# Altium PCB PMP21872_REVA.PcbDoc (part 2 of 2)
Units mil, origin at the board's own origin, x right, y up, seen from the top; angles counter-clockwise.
Board outline 2225 x 1350 mil, 4 copper layers (Top Layer, Signal Layer 1, Signal Layer 2, Bottom Layer), stack 61.6 mil thick; 75 components, 39 nets, 233 pads, 165 vias.
Unrouted connection lines stored in the file: 51.
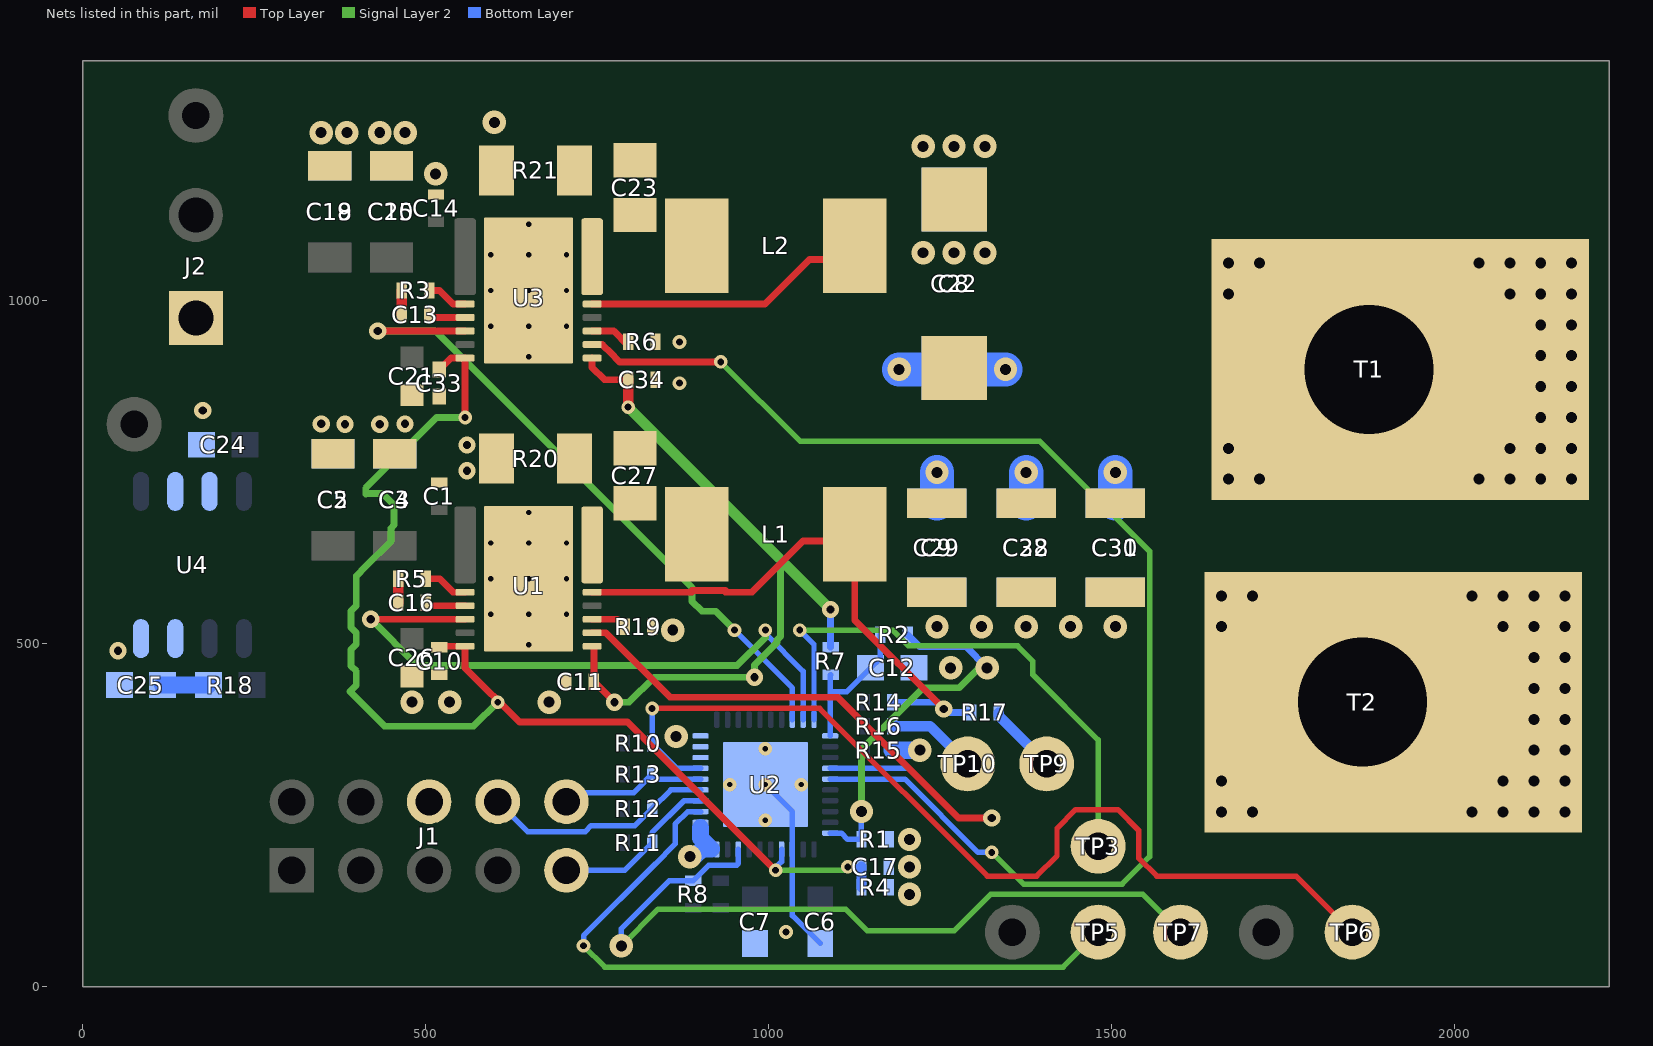
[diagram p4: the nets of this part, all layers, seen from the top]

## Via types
v1: diameter 32, hole 16, Top Layer to Bottom Layer, 56 vias
v2: diameter 34, hole 16, Top Layer to Bottom Layer, tented both sides, 45 vias
v3: diameter 19.68, hole 7.87, Top Layer to Bottom Layer, 27 vias
v4: diameter 20, hole 10, Top Layer to Bottom Layer, tented both sides, 19 vias
v5: diameter 25, hole 12, Top Layer to Bottom Layer, tented both sides, 18 vias

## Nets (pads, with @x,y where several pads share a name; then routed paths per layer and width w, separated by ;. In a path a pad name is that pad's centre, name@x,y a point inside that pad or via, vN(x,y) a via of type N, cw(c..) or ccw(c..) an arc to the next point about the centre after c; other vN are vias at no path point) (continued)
GND: C1.2 C2.2 C3.2 C4.2 C5.2 C6.2 C7.2 C8.2 C9.2 C10.2 C11.2 C12.2 C14.2 C15.2 C17.2 C18.2 C19.2 C20.2 C21.2 C22.2 C24.2 C25.2 C26.2 C28.2 C29.2 C30.2 C31.2 C32.2 C33.2 C34.2 J1.6 J2.1 R1.1 R4.1 R6.1 R15.1 R19.1 R20.2 R21.2 T2.1 U1.13@650,595 U2.13 U2.20 U2.21 U2.22 U2.28 U2.29 U2.30 U2.41@995,295 U3.13@650,1015 U4.3 U4.4 | length 378.2
  Bottom Layer w8: v3(995,295) 1034.37,255.63 U2.13@1034.37,200.51 1034.37,104.13 C6.2@1075,63.5
  Bottom Layer w25: v2(885,190) 891.77,190 902.97,201.2 916.44,201.2 900.51,217.13 U2.21@900.51,224.13 900.51,232.13 ; R15.1@1180,345 v2(1220,345)
  other v1: 1660,255 1705,255 2025,255 2070,255 2115,255 2160,255 1660,300 2070,300 2115,300 2160,300 2115,345 2160,345 2115,390 2160,390 2115,435 2160,435 2115,480 2160,480 1660,525 2070,525 2115,525 2160,525 1660,570 1705,570 2025,570 2070,570 2115,570 2160,570
  other v2: 1205,135 1205,175 1205,215 865,365 480,415 535,415 680,415 1265,465 860,520 1245,525 1310,525 1375,525 1440,525 1505,525 1225,1070 1270,1070 1315,1070 514.5,1185 1225,1225 1270,1225 1315,1225 347.7,1245 385.09,1245 433,1245 470,1245 600,1260
  other v3: 995,242.83 942.83,295 1047.17,295 995,347.17 650,498.54 594.88,543.03 650,543.03 705.12,543.03 594.88,595 650,595 705.12,595 594.88,646.97 650,646.97 705.12,646.97 650,691.46 650,918.54 594.88,963.03 650,963.03 705.12,963.03 594.88,1015 650,1015 705.12,1015 594.88,1066.97 650,1066.97 705.12,1066.97 650,1111.46
  other v4: 1025,80 870,880 870,940
  other v5: 51.73,490 560,752.27 560,790 382.26,820 433,820 347.7,820.66 470,820.66 175,840
Gnd_remote: R16.2 TP10.1 | length 132.8
  Bottom Layer w15: R16.2@1180,380 1235,380 TP10.1@1290,325
NetC13_1: C13.1 U3.9 | length 54.3
  Top Layer w10: C13.1@505,980 509.38,975.62 U3.9@557.48,975.62
NetC13_2: C13.2 R3.1 | length 35
  Top Layer w15: C13.2@465,980 R3.1@465,1015
NetC16_1: C16.1 U1.9 | length 59.3
  Top Layer w10: C16.1@500,560 504.38,555.62 U1.9@557.48,555.62
NetC16_2: C16.2 R5.1 | length 35
  Top Layer w15: C16.2@460,560 R5.1@460,595
NetC23_1: C23.1 L2.1 U3.6
NetC23_2: C23.2 R21.1
NetC25_1: C25.1 R18.1 | length 67
  Bottom Layer w25: C25.1@116.5,440 R18.1@183.5,440
NetC27_1: C27.1 L1.1 U1.6
NetC27_2: C27.2 R20.1
NetR1_2: R1.2 R2.2 U2.10 | length 548.5
  Signal Layer 2 w10: v2(1135,255.63) 1135,346 1225,436 1277.01,436 1306.01,465 v2(1318.3,465)
  Bottom Layer w8: U2.10@1089.49,224.13 1105.87,224.13 1115,215 R1.2@1135,215 v2(1135,255.63)
  Bottom Layer w10: R2.2@1202.56,513.06 1219.62,496 1287.3,496 v2(1318.3,465)
NetR3_2: R3.2 U3.8 | length 60.6
  Top Layer w10: R3.2@505,1015 520.18,1015 539.87,995.31 U3.8@557.48,995.31
NetR5_2: R5.2 U1.8 | length 65.6
  Top Layer w10: R5.2@500,595 520.18,595 539.87,575.31 U1.8@557.48,575.31
NetR6_2: R6.2 U3.3 | length 61.1
  Top Layer w10: U3.3@742.52,955.93 774.07,955.93 R6.2@795,935
NetR19_2: R19.2 U1.3 | length 52
  Top Layer w10: U1.3@742.52,535.93 779.07,535.93 R19.2@790,525
NetU4_6: U4.6 U4.7
PMB_ALERT#: J1.8 R12.1 U2.25 | length 338.6
  Bottom Layer w8: J1.8@605,270 648.48,226.52 732.74,226.52 741.22,235 805,235 R12.1@830,260 857.13,287.13 U2.25@900.51,287.13
PMB_CLK: J1.9 R11.1 U2.24 | length 246.3
  Bottom Layer w8: J1.9@705,170 790,170 R11.1@830,210 830,224.94 876.43,271.38 U2.24@900.51,271.38
PMB_DIO: J1.10 R13.1 U2.26 | length 215
  Bottom Layer w8: J1.10@705,270 718,283 803,283 R13.1@830,310 837.13,302.87 U2.26@900.51,302.87
PWM1: U1.10 U2.39 | length 921.5
  Top Layer w10: v5(420,535.93) U1.10@557.48,535.93
  Signal Layer 2 w10: v5(420,535.93) 487.63,468.3 953.93,468.3 995,509.37 v4(995,520)
  Bottom Layer w8: v4(995,520) 995,515 1050.12,459.88 U2.39@1050.12,389.49
PWM2: U2.38 U3.10 | length 1005.2
  Top Layer w10: v5(430,955.93) U3.10@557.48,955.93
  Signal Layer 2 w10: v5(430,955.93) 514.07,955.93 888.1,581.9 888.1,562 902.45,547.65 922.35,547.65 v4(950,520)
  Bottom Layer w8: v4(950,520) 1034.37,435.63 U2.38@1034.37,389.49
TSEN: C10.1 C17.1 C33.1 R4.2 U1.12 U2.14 U3.12 | length 1773.1
  Top Layer w10: C10.1@520,495 521.55,496.55 U1.12@557.48,496.55 557.48,465.02 636.5,386 794,386 v4(1010,170) ; C33.1@520,899.68 536.87,916.55 U3.12@557.48,916.55 v4(557.48,830.02)
  Signal Layer 2 w8: v4(1010,170) 1110,170 v4(1115,175)
  Signal Layer 2 w10: v4(557.48,830.02) 515.77,830.02 412.6,726.85 412.6,718.61 412.99,719 437.01,719 452.5,703.51 454,702.01 454,677.99 454,672.99 449.5,668.49 449.5,649.5 412.6,612.6 398.86,598.86 398.86,555.81 391,547.94 391,523.92 398.86,516.05 398.86,499.87 391,492.01 391,467.98 398.86,460.12 398.86,439.81 389.56,430.5 440.06,380 570,380 v4(605,415)
  Bottom Layer w8: v4(1010,170) 1010,174.06 1018.62,182.68 U2.14@1018.62,200.51 ; v4(1115,175) C17.1@1135,175
  Bottom Layer w15: R4.2@1135,145 C17.1@1135,175
VCCIO_EN: TP5.1 U2.23 | length 1071.8
  Signal Layer 2 w8: v4(730,60) 761,29 1429,29 TP5.1@1480,80 ; TP5.1@1472.5,87.5 TP5.1@1480,95
  Bottom Layer w8: v4(730,60) 730,75 833.79,178.79 833.84,178.79 863.5,208.44 863.5,237.23 881.9,255.63 U2.23@900.51,255.63
VOUT: C8.1 C9.1 C22.1 C28.1 C29.1 C30.1 C31.1 C32.1 L1.2 L2.2 R14.1 R17.1 T1.1 U1.5 U3.5 | length 1550.7
  Top Layer w10: U1.5@742.52,575.31 888.1,575.31 888.1,578 937.1,578 937.1,575.31 975.31,575.31 1050,650 L1.2@1125.16,650 ; U3.5@742.52,995.31 994.68,995.31 1059.37,1060 L2.2@1125.16,1060 ; L1.2@1125.16,660 L1.2@1125.16,650 ; v5(1255,405) 1125.16,534.84 L1.2@1125.16,650
  Bottom Layer w10: R14.1@1180,415 1245,415 v5(1255,405) 1260,400 R17.1@1295,400
  Bottom Layer w50: v2(1190,900) C22.1@1270,900 ; C29.1@1245,704.96 v2(1245,750) ; C22.1@1270,902.17 C22.1@1270,900 ; v2(1345,900) C22.1@1270,900 ; C32.1@1375,704.96 v2(1375,750) ; C31.1@1505,704.96 v2(1505,750)
  other v1: 1670,740 1715,740 2035,740 2080,740 2125,740 2170,740 1670,785 2080,785 2125,785 2170,785 2125,830 2170,830 2125,875 2170,875 2125,920 2170,920 2125,965 2170,965 1670,1010 2080,1010 2125,1010 2170,1010 1670,1055 1715,1055 2035,1055 2080,1055 2125,1055 2170,1055
Vout_CSP1: U1.2 U2.4 | length 960.1
  Top Layer w10: U1.2@742.52,516.24 762.29,516.24 856.23,422.3 1100.12,422.3 1276.21,246.22 v5(1325,246.22)
  Bottom Layer w8: U2.4@1089.49,318.62 1203.8,318.62 1276.59,245.84 v5@1324.62,245.84
  Bottom Layer w10: v5@1324.62,245.84 v5(1325,246.22)
Vout_CSP2: U2.5 U3.2 | length 1927.7
  Top Layer w10: U3.2@742.52,936.24 757.29,936.24 760.06,933.47 760.12,933.47 768.3,925.29 768.3,925.23 782.53,911 v4(929.91,911)
  Signal Layer 2 w8: v4(929.91,911) 1045.91,795 1395,795 1555,635 1555,190 1515,150 1371.22,150 v4(1325,196.22)
  Bottom Layer w8: U2.5@1089.49,302.87 1198.34,302.87 1304.99,196.22 v4(1325,196.22)
Vout_SKIP: TP3.1 U2.40 | length 811.9
  Signal Layer 2 w8: v4@1040,520 v4(1045,520) 1180.44,520 1203.44,497 1362.6,497 1385,474.6 1385,455 1480,360 TP3.1@1480,205
  Bottom Layer w8: v4(1045,520) 1065.87,499.13 U2.40@1065.87,389.49
VR_FAULT#: R10.1 TP6.1 U2.27 | length 1419.3
  Top Layer w8: v4(830,405.98) 1074.02,405.98 1318.62,161.38 1390.36,161.38 1420,191.01 1420,231.22 1447.24,258.46 1508.85,258.46 1538.93,228.38 1538.93,187.93 1565.48,161.38 1768.62,161.38 TP6.1@1850,80
  Bottom Layer w8: v4(830,405.98) R10.1@830,355 866.38,318.62 U2.27@900.51,318.62
VR_HOT: R8.1 TP7.1 U2.18 | length 1150.3
  Signal Layer 2 w8: v2(785,60) 838.52,113.52 1111.88,113.52 1143.4,82 1270.39,82 1323.39,135 1545,135 TP7.1@1600,80
  Bottom Layer w8: v2(785,60) 785,85 855,155 R8.1@890,155 912.7,177.7 953.07,177.7 955.63,180.26 U2.18@955.63,200.51
VREF: C12.1 R2.1 R7.1 U2.1 | length 216.7
  Bottom Layer w8: U2.1@1089.49,365.87 1089.49,429.76 1089.72,430 ; R7.1@1090,455 1089.49,454.49 1089.49,430.24 1089.72,430 ; R2.1@1162.56,513.06 1162.56,479.06 C12.1@1148.5,465 1113.5,430 1089.72,430
VREF_P: C11.1 C34.1 R7.2 U1.1 U3.1 | length 1083.2
  Top Layer w10: U1.1@742.52,496.55 745,494.07 C11.1@745,445 v5(775,415) ; U3.1@742.52,916.55 742.52,902.8 760.32,885 C34.1@795,885
  Top Layer w15: v4(795,845) C34.1@795,885
  Signal Layer 2 w10: v5(775,415) 796.17,415 832.47,451.3 v5(979.1,451.3) 979.1,469.43 1012,502.33 1012,505.89 1017,510.89 1017,609.05 1023.98,616.02
  Signal Layer 2 w15: v4(795,845) 1023.98,616.02 v5(1090,550)
  Bottom Layer w10: R7.2@1090,495 v5(1090,550)
Vremote+: R17.2 TP9.1 | length 104
  Bottom Layer w15: R17.2@1335,400 1335,395 TP9.1@1405,325
pads on no net: J1.1 J1.2 J1.3 J1.4 J1.5 J1.7 U1.13@618.31,517.05 U1.13@618.31,569.02 U1.13@618.31,620.98 U1.13@618.31,672.95 U1.13@681.69,517.05 U1.13@681.69,569.02 U1.13@681.69,620.98 U1.13@681.69,672.95 U2.7 U2.8 U2.9 U2.15 U2.19 U2.31 U2.32 U2.33 U2.34 U2.35 U2.36 U2.37 U2.41@964.09,264.09 U2.41@964.09,325.91 U2.41@1025.91,264.09 U2.41@1025.91,325.91 U3.13@618.31,937.05 U3.13@618.31,989.02 U3.13@618.31,1040.98 U3.13@618.31,1092.95 U3.13@681.69,937.05 U3.13@681.69,989.02 U3.13@681.69,1040.98 U3.13@681.69,1092.95 U4.5

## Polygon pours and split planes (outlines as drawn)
12Vin on Top Layer "TOP_LAYER_12VIN_P030" (solid, remove dead copper, pour order 30): 113.41,1325 113.9,1324.51 215,1324.51 215,1263.15 210.97,1259.12 327.96,1142.14 578.4,1142.14 577.18,1140.92 577.18,1004.16 540.48,1004.16 520,1024.64 520,1040 332.95,1040 327.96,1035 327.96,722.04 335,715 335.08,715.08 580,715.08 580,577.13 577.13,580 545,580 505,620 295,620 210,705 210,1075 112.86,1075 113.41,1075.54
GND on Top Layer "TOP_LAYER_GND_P040" (solid, remove dead copper, pour order 40): 0,0 0,1330 2225,1330 2225,0
GND on Signal Layer 1 "SIGNAL_LAYER_1_GND_P042" (solid, remove dead copper, pour order 42): 0,0 0,1330 2225,1330 2225,0
GND on Signal Layer 2 "SIGNAL_LAYER_2_GND_P044" (solid, remove dead copper, pour order 44): 0,0 0,1330 2225,1330 2225,0
12Vin on Bottom Layer "BOTTOM_LAYER_12VIN_P038" (solid, remove dead copper, pour order 38): 113.41,1325 113.9,1324.51 215,1324.51 215,1263.15 210.97,1259.12 327.96,1142.14 578.4,1142.14 577.18,1140.92 577.18,1004.16 540.48,1004.16 520,1024.64 520,1040 332.95,1040 327.96,1035 327.96,722.04 335,715 335.08,715.08 580,715.08 580,577.13 577.13,580 545,580 505,620 295,620 210,705 210,1075 112.86,1075 113.41,1075.54
GND on Bottom Layer "BOTTOM_LAYER_GND_P046" (solid, remove dead copper, pour order 46): 0,0 0,1330 2225,1330 2225,0

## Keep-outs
Keep-Out Layer:
  text ".Layer_Name" at 577,-858.49 h60

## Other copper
Top Layer:
  region net VOUT: 1075,1155 1075,590 1170,590 1230,650 2195,650 2195,1100 1640,1100 1575,1035 1210,1035 1180,1065 1180,1155
  region net NetC23_2: 690,1230 690,1155 755,1155 775,1175 840,1175 840,1230
  region net NetC23_1: 730,1010 730,1110 775,1155 945,1155 945,1010
  region net NetC27_2: 690,810 690,735 755,735 775,755 840,755 840,810
  region net NetC27_1: 730,590 730,690 775,735 945,735 945,590
  text ".Layer_Name" at 577,-858.49 h60
Bottom Layer:
  region net VOUT: 1165,980 1165,650 2195,650 2195,1100 1640,1100 1520,980
  region net 5V: 175,535 175,480 195,480 220,455 220,420 270,420 270,535
  region net NetU4_6: 125,750 125,695 195,695 195,750
  region net 12Vin: 1050,215 1050,105 1095,105 1095,185 1065,215
  text ".Layer_Name" at 577,-858.49 h60

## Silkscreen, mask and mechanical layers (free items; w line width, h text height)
Top Overlay:
  text ".Layer_Name" at 577,-858.49 h60
Bottom Overlay:
  lines w10: 1200,335 1240,375 1355,375
  text ".Layer_Name" at 577,-858.49 h60
Top Paste:
  text ".Layer_Name" at 577,-858.49 h60
Bottom Paste:
  text ".Layer_Name" at 577,-858.49 h60
Top Solder:
  text ".Layer_Name" at 577,-858.49 h60
  text ".Layer_Name" at 577,-858.49 h60
Bottom Solder:
  text ".Layer_Name" at 577,-858.49 h60
Drill Guide:
  text ".Layer_Name" at 577,-858.49 h60
M1 Board Outline:
  the board outline again, w1
  text ".Layer_Name" at 577,-858.49 h60
M2 Board Dimensions:
  rectangle: 125,-400 500,-275
  rectangle: 0,-275 125,-150
  lines w7: 0,-275 1000,-275 ; 125,-400 125,-150 ; 250,-400 250,-150 ; 500,-400 500,-150 ; 750,-400 750,-150 ; 0,-400 0,-150 1000,-150 1000,-400 0,-400
  text ".Layer_Name" at 577,-858.49 h60
M3 3D STEP Top:
  text ".Layer_Name" at 577,-858.49 h60
M4 3D STEP Bottom:
  text ".Layer_Name" at 577,-858.49 h60
M5 Assembly Top:
  lines w10: -292,-930.17 6308,-930.17 ; -292,-726.83 6310,-726.83 ; -292,-523.5 -292,-1133.5 3713,-1133.5 6310,-1133.5 6310,-523.5 -291.5,-523.5 -291.5,-1133.5 1284,-1133.5 ; 2173,-1133.5 2173,-523.5 ; 3440,-726.83 3440,-523.5 ; 4280,-726.83 4280,-523.5 ; 4902,-1140 4902,-937.17
  text "COMPONENTS MARKED 'DNP' SHOULD NOT BE POPULATED." at 1153.5,-318.5 h60
  text "ASSEMBLY VARIANT:" at 1153,-434 h60
  text ".VariantName" at 2189,-434 h60
  text "PCB VIEWED FROM TOP SIDE" at -228.5,-655.67 h60
  text "BOARD #:" at 2248,-655.67 h60
  text ".PRJ_Number" at 2793.5,-655.67 h60
  text "REV:" at 3638,-655.67 h60
  text ".PCB_Rev" at 3929.5,-655.67 h60
  text "SVN REV:" at 4476,-655.67 h60
  text ".VersionControl_RevNumber" at 4982,-655.67 h60
  text "TID #:" at 2248,-859 h60
  text ".TID" at 2793.5,-859 h60
  text "PLOT NAME =" at -228.5,-1064.34 h60
  text ".plot_File_Name" at 577,-1064.34 h60
  text "GENERATED    :" at 2250,-1064.34 h60
  text ".Print_Date" at 3119.5,-1064.34 h60
  text ".Print_Time" at 3848.5,-1064.34 h60
  text "TEXAS INSTRUMENTS" at 5113,-1064.34 h60
M6 Assembly Bottom:
  lines w10: -292.5,-727.33 6309.5,-727.33 ; -290.5,-930.67 6309.5,-930.67 ; 1115.5,-1140.5 1115.5,-937.67 ; 1737.5,-727.33 1737.5,-524 ; 2577.5,-727.33 2577.5,-524 ; 3844.5,-1134 3844.5,-524 ; 4733.5,-1134 6309,-1134 6309,-524 -292.5,-524 -292.5,-1134 2304.5,-1134 6309.5,-1134 6309.5,-524
  text "COMPONENTS MARKED 'DNP' SHOULD NOT BE POPULATED." at 6102,-318 h60
  text ".VariantName" at 5058,-434 h60
  text "ASSEMBLY VARIANT:" at 6097,-434 h60
  text ".VersionControl_RevNumber" at 1035.5,-656.17 h60
  text "SVN REV:" at 1541.5,-656.17 h60
  text ".PCB_Rev" at 2088,-656.17 h60
  text "REV:" at 2379.5,-656.17 h60
  text ".PRJ_Number" at 3224,-656.17 h60
  text "BOARD #:" at 3769.5,-656.17 h60
  text "PCB VIEWED FROM BOTTOM SIDE" at 6246,-656.17 h60
  text ".TID" at 3224,-859.5 h60
  text "TID #:" at 3769.5,-859.5 h60
  text "TEXAS INSTRUMENTS" at 904.5,-1064.84 h60
  text ".Print_Time" at 2169,-1064.84 h60
  text ".Print_Date" at 2898,-1064.84 h60
  text "GENERATED    :" at 3767.5,-1064.84 h60
  text ".plot_File_Name" at 5440.5,-1064.84 h60
  text "PLOT NAME =" at 6246,-1064.84 h60
M9 Title Sheet:
  drawing of 57 lines, arcs and shapes, not listed
  text "1" at 739.84,8036.5 h70
  text "2" at 3235.5,8036.5 h70
  text "3" at 5724.84,8036.5 h70
  text "4" at 8231.51,8036.5 h70
  text "5" at 10730.5,8036.5 h70
  text "6" at 13235.5,8036.5 h70
  text "A" at -416.5,6893.5 h70
  text "A" at 14383.5,6893.5 h70
  text "B" at -416.5,4513.5 h70
  text "B" at 14383.5,4513.5 h70
  text "C" at -416.5,2138.5 h70
  text "C" at 14383.5,2138.5 h70
  text "PROJECT TITLE:" at 11343.5,277.5 h45
  text ".PRJ_Title" at 11393.5,144.17 h70
  text "DESIGNED FOR:" at 11343.5,-23.5 h45
  text ".PRJ_Customer" at 11393.5,-163.5 h70
  text "D" at -416.5,-231.5 h70
  text "D" at 14383.5,-231.5 h70
  text "FILE NAME:" at 11343.5,-323.5 h45
  text ".PCB_File_Name_No_Path" at 11393.5,-443.5 h70
  text "Texas Instruments (TI) and/or its licensors do not warrant the accuracy or completeness of this specification" at 6374,-605.34 h45
  text "ENGINEER:" at 11343.5,-613.5 h45
  text "LAYOUT BY:" at 12848.5,-613.5 h45
  text "or any information contained therein. TI and/or its licensors do not warrant that this design will meet" at 6329.01,-718 h45
  text ".PRJ_Engineer" at 11393.5,-768.49 h70
  text ".PCB_Layout" at 12899,-768.49 h70
  text "the specifications, will be suitable for your application or fit for any particular purpose, or will operate in" at 6329.01,-830.67 h45
  text ".Layer_Name" at 577,-858.49 h60
  text "ALTIUM DESIGNER VERSION:" at 12848.5,-923.5 h45
  text "an implementation. TI and/or its licensors do not warrant that the design is production worthy. You should" at 6329.01,-943.33 h45
  text "completely validate and test your design implementation to confirm the system functionality for your application." at 6374,-1056 h45
  text ".print_Scale" at 11393.5,-1056.83 h70
  text ".Application_BuildNumber" at 12899,-1056.83 h70
  text "1" at 739.84,-1263.5 h70
  text "2" at 3235.5,-1263.5 h70
  text "3" at 5724.84,-1263.5 h70
  text "4" at 8231.51,-1263.5 h70
  text "5" at 10730.5,-1263.5 h70
  text "6" at 13235.5,-1263.5 h70
M10 Fab Notes:
  drawing of 189 lines, arcs and shapes, not listed
  text "DESIGN INFORMATION" at 12382.02,6356.17 h60
  text "MIN. TRACK WIDTH:" at 11737.46,6224.05 h60
  text "8" at 12833.7,6224.05 h60
  text "MIL" at 12988.46,6224.05 h60
  text "MIN. CLEARANCE:" at 11737.46,6099.92 h60
  text "0.2" at 12773.7,6099.93 h60
  text "mm" at 12988.46,6099.92 h60
  text "MIN. VIA PAD SIZE:" at 11737.46,5975.8 h60
  text "24" at 12803.71,5975.8 h60
  text "MIL" at 12988.46,5975.8 h60
  text "0.05mm (2MIL)" at 12432.46,5845.9 h60
  text "MINIMUM ANNULAR RING" at 11408.23,5837.67 h60
  text "EXTERNAL" at 13140.46,5837.67 h60
  text "PER" at 11608.23,5727.55 h60
  text "IPC-D-275 CLASS 2 LEVEL C" at 11828.23,5727.54 h60
  text "MIL, HOLES" at 13316.46,5627.07 h60
  text "+/-" at 12924,5618.48 h60
  text "+/-" at 13778,5618.48 h60
  text "REGISTRATION TOLERANCES:" at 11408.23,5617.42 h60
  text "METAL" at 12608,5617.42 h60
  text "5" at 13184.2,5617.42 h60
  text "3" at 14017.2,5617.42 h60
  text "MIL" at 14133.46,5617.42 h60
  text "HOLE SIZE TOLERANCE (UNLESS OTHERWISE SPECIFIED):" at 11408.23,5519.1 h60
  text "+/-" at 13778,5516.23 h60
  text "3" at 14017.2,5515.17 h60
  text "MIL" at 14133.46,5515.17 h60
  text "MATERIAL:" at 11333.46,5377.52 h60
  text "FR-4 High Tg" at 12319.9,5249 h60
  text "X" at 12175.46,5241.01 h60
  text "FR-408" at 11754.46,5236.49 h60
  text "OTHER" at 13242.46,5236.49 h60
  text "40 MIL (1.0mm) +/-10%" at 12074.56,5093.46 h60
  text "X" at 11954.46,5091.01 h60
  text "THICKNESS:" at 11408.23,5085.24 h60
  text "OTHER" at 13359.46,5085.24 h60
  text "TOLERANCE:" at 11408.23,4946.92 h60
  text "X" at 12256.46,4946.92 h60
  text "ANSI IPC-6012 TYPE 3 CLASS 2" at 12434.48,4946.92 h60
  text "OTHER +/-" at 12434.46,4802.73 h60
  text "BOW & TWIST:" at 11408.23,4657.54 h60
  text "X" at 12256.46,4657.54 h60
  text "ANSI IPC-6012 TYPE 3 CLASS 2" at 12434.48,4657.54 h60
  text "OTHER +/-" at 12434.46,4510.85 h60
  text "DRILLING:" at 11333.46,4380.23 h60
  text "NC_DRILL FILES" at 13094.46,4275.04 h60
  text "REFERENCE:" at 11408.23,4271.1 h60
  text "X" at 12065.46,4271.01 h60
  text "AS SHOWN" at 12243.46,4271.1 h60
  text "X" at 12966.46,4271.1 h60
  text "OTHER" at 13392.46,4128.85 h60
  text "PTH COPPER THICKNESS:" at 11407.91,4125.32 h60
  text "X" at 12547.14,4125.32 h60
  text "20-30 um" at 12675.14,4125.32 h60
  text "BOARD FINISH:" at 11333.46,3977.73 h60
  text "SILKSCREEN:" at 11488.68,3867.6 h60
  text "X" at 12446.46,3867.6 h60
  text "TOP" at 12563.46,3867.6 h60
  text "X" at 12956.46,3867.6 h60
  text "BOTTOM" at 13074.46,3867.6 h60
  text "SILKSCREEN COLOR:" at 11488.68,3712.41 h60
  text "X" at 12445.46,3712.41 h60
  text "WHITE" at 12563.46,3712.41 h60
  text "OTHER" at 13074.46,3712.41 h60
  text "X" at 12576.46,3568.96 h60
  text "GREEN" at 12694.46,3568.96 h60
  text "OTHER" at 13312.46,3568.96 h60
  text "SOLDER RESIST COLOR:" at 11488.68,3562.1 h60
  text "X" at 12576.46,3414.71 h60
  text "MATTE" at 12694.46,3414.71 h60
  text "SEMI-GLOSS" at 13312,3414.07 h60
  text "IMMERSION GOLD (ENIG)" at 12394.46,3241.94 h60
  text "ENEPIG" at 13732,3234.72 h60
  text "SURFACE FINISH:" at 11333.46,3233.72 h60
  text "X" at 12216.46,3233.72 h60
  text "IMM. TIN/SILVER OR EQUIV" at 11663,3096.4 h60
  text "OTHER" at 13094.46,3092.47 h60
  text "ARRAY/PANEL:" at 11333.46,2937.09 h60
  text "CUT AND TRIM PER M1 BOARD OUTLINE" at 12394.46,2928.87 h60
  text "N.C. ROUTE" at 12394.46,2792.9 h60
  text "X" at 13082.46,2792.9 h60
  text "V. SCORE" at 13260.46,2792.9 h60
  text "CERTIFICATION:" at 11333.46,2663.77 h60
  text "MATERIALS AND WORKMANSHIP FOR ALL PCBS" at 12058.46,2663.77 h60
  text "TO MEET OR EXCEED THE REQUIREMENTS OF:" at 12058.46,2569.71 h60
  text "X" at 11695.97,2441.08 h60
  text "ANSI IPC-A-600F CLASS ->" at 11823.96,2441.08 h60
  text "X" at 13471.97,2441.08 h60
  text "2" at 13581.96,2441.08 h60
  text "1" at 13266.96,2439.58 h60
  text "3" at 13935.96,2439.58 h60
  text "X" at 12507.97,2293.39 h60
  text "RoHS" at 12635.96,2293.39 h60
  text "OTHER" at 13280.36,2293.39 h60
  text "PER ORDER" at 13677.42,2293.39 h60
  text "ALL BOARDS MUST MEET OR EXCEED UL94-V0 REQUIREMENTS." at 11361,2139.57 h60
  text "PCB MUST BEAR THE UL94V-0 UL REGISTERED MATERIAL ID NUMBER" at 11361,2023.5 h60
  text "ADDITIONAL REQUIREMENTS:" at 11333.46,1854.08 h60
  text "MICROSECTION:" at 11408.23,1746.95 h60
  text "YES" at 12313.96,1746.95 h60
  text "REQUIRED" at 13175.46,1602.62 h60
  text "BARE BOARD ELEC. TEST:" at 11408.23,1599.76 h60
  text "NONE" at 12713.96,1599.76 h60
  text "X" at 13057.46,1599.76 h60
  text "PER ORDER" at 13767.46,1599.76 h60
  text "XX MIL VIAS REQUIRE NON-CONDUCTIVE FILL AND PLANARIZE" at 11576.38,1394.82 h59
  text "XX MIL VIAS REQUIRE CONDUCTIVE FILL AND PLANARIZE" at 11584.38,1290.84 h60
  text "OUTER XX MIL VIAS REQUIRE 50 OHM SINGLE-ENDED IMPEDANCE" at 11583.39,1127.46 h58
  text "LAYER 2 & 3 (INNER LAYERS) XX MIL WIDE, XX MIL SPACE / TRACES REQUIRE 100 OHM DIFFERENTIAL IMPEDANCE" at 11575.39,891.74 h60
  text ".Layer_Name" at 577,-858.49 h60
M11 Gerber Information:
  lines w10: -292,-930.17 6308,-930.17 ; -292,-726.83 6310,-726.83 ; -292,-523.5 -292,-1133.5 3713,-1133.5 6310,-1133.5 6310,-523.5 -291.5,-523.5 -291.5,-1133.5 1284,-1133.5 ; 2173,-1133.5 2173,-523.5 ; 3440,-726.83 3440,-523.5 ; 4280,-726.83 4280,-523.5 ; 4902,-1140 4902,-937.17
  text "ALL ARTWORK VIEWED FROM TOP SIDE" at -228.5,-655.67 h60
  text "BOARD #:" at 2248,-655.67 h60
  text ".PRJ_Number" at 2793.5,-655.67 h60
  text "REV:" at 3638,-655.67 h60
  text ".PCB_Rev" at 3929.5,-655.67 h60
  text "SVN REV:" at 4476,-655.67 h60
  text ".VersionControl_RevNumber" at 4982,-655.67 h60
  text "LAYER NAME =" at -228.5,-858.49 h60
  text "TID #:" at 2248,-859 h60
  text ".TID" at 2793.5,-859 h60
  text "PLOT NAME =" at -228.5,-1064.34 h60
  text ".plot_File_Name" at 577,-1064.34 h60
  text "GENERATED    :" at 2250,-1064.34 h60
  text ".Print_Date" at 3119.5,-1064.34 h60
  text ".Print_Time" at 3848.5,-1064.34 h60
  text "TEXAS INSTRUMENTS" at 5113,-1064.34 h60
M12 Stackup:
  drawing of 295 lines, arcs and shapes, not listed
  text "Layer" at 9760.34,8280 h60
  text "Name" at 10170.26,8280 h60
  text "Material" at 11110,8280 h60
  text "Thickness" at 11969.76,8280 h60
  text "Constant" at 12619.6,8280 h60
  text "Board Layer Stack" at 13189.46,8280 h60
  text "1" at 9760.34,8160 h60
  text "Top Overlay" at 10170.26,8160 h60
  text "2" at 9760.34,8040 h60
  text "Top Solder" at 10170.26,8040 h60
  text "Solder Resist" at 11110,8040 h60
  text "0.40mil" at 11969.76,8040 h60
  text "3.5" at 12619.6,8040 h60
  text "3" at 9760.34,7920 h60
  text "Top Layer" at 10170.26,7920 h60
  text "Copper" at 11110,7920 h60
  text "1.40mil" at 11969.76,7920 h60
  text "4" at 9760.34,7800 h60
  text "Dielectric 1" at 10170.26,7800 h60
  text "FR-4" at 11110,7800 h60
  text "8.00mil" at 11969.76,7800 h60
  text "4.2" at 12619.6,7800 h60
  text "5" at 9760.34,7680 h60
  text "Signal Layer 1" at 10170.26,7680 h60
  text "Copper" at 11110,7680 h60
  text "1.40mil" at 11969.76,7680 h60
  text "6" at 9760.34,7560 h60
  text "Dielectric 2" at 10170.26,7560 h60
  text "FR-4" at 11110,7560 h60
  text "40.00mil" at 11969.76,7560 h60
  text "4.2" at 12619.6,7560 h60
  text "7" at 9760.34,7440 h60
  text "Signal Layer 2" at 10170.26,7440 h60
  text "Copper" at 11110,7440 h60
  text "1.40mil" at 11969.76,7440 h60
  text "8" at 9760.34,7320 h60
  text "Dielectric 3" at 10170.26,7320 h60
  text "FR-4" at 11110,7320 h60
  text "8.00mil" at 11969.76,7320 h60
  text "4.2" at 12619.6,7320 h60
  text "9" at 9760.34,7200 h60
  text "Bottom Layer" at 10170.26,7200 h60
  text "Copper" at 11110,7200 h60
  text "1.40mil" at 11969.76,7200 h60
  text "10" at 9760.34,7080 h60
  text "Bottom Solder" at 10170.26,7080 h60
  text "Solder Resist" at 11110,7080 h60
  text "0.40mil" at 11969.76,7080 h60
  text "3.5" at 12619.6,7080 h60
  text "11" at 9760.34,6960 h60
  text "Bottom Overlay" at 10170.26,6960 h60
  text ".Layer_Name" at 577,-858.49 h60
M13 Component Bodies Top:
  text ".Layer_Name" at 577,-858.49 h60
M14 Component Bodies Bottom:
  text ".Layer_Name" at 577,-858.49 h60
M15 Courtyards Top:
  text ".Layer_Name" at 577,-858.49 h60
M16 Courtyards Bottom:
  text ".Layer_Name" at 577,-858.49 h60
Drill Drawing:
  text ".Layer_Name" at 577,-858.49 h60
Mechanical 17:
  text ".Layer_Name" at 577,-858.49 h60
Mechanical 18:
  text ".Layer_Name" at 577,-858.49 h60
Mechanical 19:
  text ".Layer_Name" at 577,-858.49 h60

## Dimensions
0,0 to 2225,0 on M2 Board Dimensions
0,0 to 0,1350 on M2 Board Dimensions
0,-400 to 1000,-400 on M2 Board Dimensions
